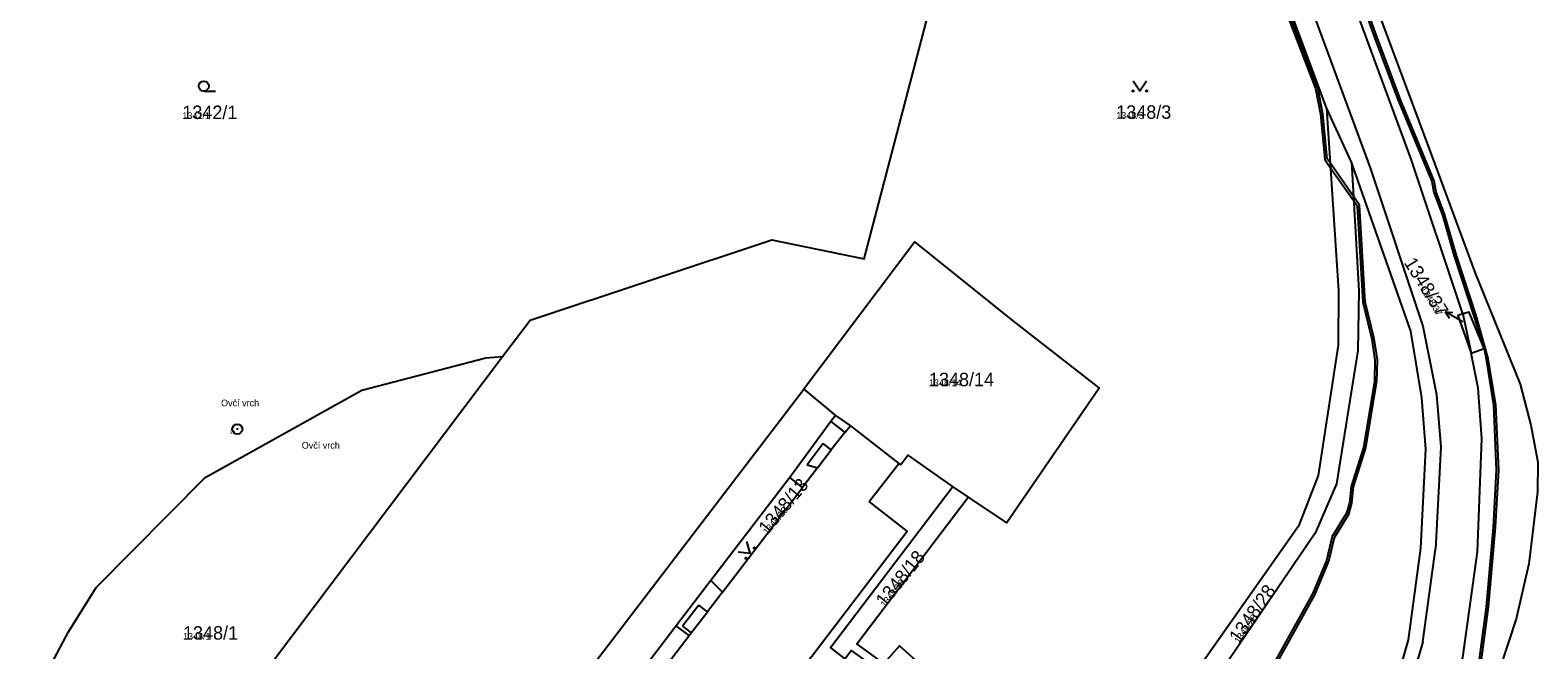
# Model space of a CAD drawing. Extents: x -763628 to -761565, y -976033 to -973833.
# Drawn here: x -762526.1 to -762302.1, y -975580.9 to -975488.8 of the extents above; entities that cross this region are included whole.
import ezdxf

# ---------------------------------------------------------------- set-up
doc = ezdxf.new("R2010")
doc.units = 0
for name, color, linetype in [('KN_cisla parcel 1000', 7, 'Continuous'), ('KN_cisla parcel 500', 7, 'Continuous'), ('KN_cisla parcel znacky', 7, 'Continuous'), ('KN_hranice parcel', 7, 'Continuous'), ('KN_popisy', 7, 'Continuous'), ('KN_vecna bremena', 7, 'Continuous'), ('KN_vnitrni kresba parcel', 7, 'Continuous'), ('KN_znacky bodu BP', 7, 'Continuous'), ('KN_znacky kultur', 7, 'Continuous')]:
    doc.layers.add(name, color=color, linetype=linetype)

msp = doc.modelspace()

# ---------------------------------------------------------------- linework, layer by layer
at = {"layer": 'KN_cisla parcel znacky'}
for p, q in [((-762313.27, -975532.17), (-762315.87, -975530.67)), ((-762315.87, -975530.67), (-762314.75, -975530.74)), ((-762315.87, -975530.67), (-762315.25, -975531.6))]:
    msp.add_line(p, q, dxfattribs=at)
at = {"layer": 'KN_hranice parcel'}
for p, q in [((-762329.78, -975508.4), (-762333.52, -975500.37)), ((-762313.26, -975530.98), (-762320.9, -975507.99)), ((-762310.99, -975542.02), (-762312, -975536.8)), ((-762411.19, -975542.16), (-762406.47, -975546.08)), ((-762413.28, -975555.29), (-762425, -975570.59)), ((-762389.05, -975556.64), (-762386.74, -975558.2)), ((-762425, -975570.59), (-762430.13, -975577.3)), ((-762430.13, -975577.3), (-762448.29, -975601.15))]:
    msp.add_line(p, q, dxfattribs=at)
for points in [[(-762320.9, -975507.99), (-762333.29, -975474.33), (-762340.09, -975455.85)], [(-762455.93, -975537.3), (-762451.86, -975531.9), (-762415.93, -975519.94), (-762402.23, -975522.78), (-762385.32, -975458.25)], [(-762333.52, -975500.37), (-762342, -975477.5), (-762348.7, -975458.93)], [(-762330.42, -975473.69), (-762317.88, -975507.36), (-762311.41, -975524.93), (-762304.73, -975541.39), (-762303.13, -975547.49), (-762302.1, -975552.98), (-762302.14, -975557.43), (-762303.44, -975568.09), (-762305.3, -975576.28), (-762307.74, -975583.66), (-762309.01, -975587.42), (-762310.14, -975590.81), (-762313.38, -975597.97), (-762313.79, -975598.72), (-762314.8, -975600.39)], [(-762333.52, -975500.37), (-762331.73, -975527.56), (-762331.77, -975535.62), (-762334.73, -975554.96), (-762337.68, -975562.5), (-762353.31, -975584.75), (-762360.52, -975596)], [(-762403.81, -975712.92), (-762399.17, -975708.68), (-762393.45, -975701.6), (-762387.86, -975693.06), (-762358.94, -975647.65), (-762334.55, -975608.66), (-762324.91, -975591.91), (-762321.34, -975579.42), (-762319.47, -975565.76), (-762318.73, -975551.05), (-762319.32, -975543.45), (-762320.98, -975533.54), (-762329.78, -975508.4)], [(-762329.78, -975508.4), (-762328.72, -975527.52), (-762328.86, -975536.39), (-762332.01, -975556.21), (-762335.17, -975563.53), (-762350.94, -975586.68), (-762357.89, -975597.63)], [(-762386.74, -975558.2), (-762381.07, -975562.01), (-762367.28, -975541.95), (-762380.07, -975531.99), (-762394.69, -975520.26), (-762411.19, -975542.16)], [(-762313.26, -975530.98), (-762314, -975531.2), (-762312, -975536.8)], [(-762312, -975536.8), (-762310.1, -975536.1), (-762312.3, -975530.7), (-762313.26, -975530.98)], [(-762553.82, -975649.08), (-762540.26, -975615.89), (-762533.07, -975601.88), (-762520.45, -975578.19), (-762516.33, -975571.64), (-762500.14, -975555.29), (-762476.88, -975542.28), (-762458.41, -975537.49), (-762455.93, -975537.3)], [(-762527.07, -975640.34), (-762529.3, -975634.7), (-762455.93, -975537.3)], [(-762512.11, -975678.16), (-762511.09, -975674.43), (-762503.29, -975662.52), (-762500.18, -975658.38), (-762473.49, -975623.68), (-762452.78, -975596.61), (-762429.65, -975566.34), (-762411.19, -975542.16)], [(-762391.57, -975714.65), (-762389.96, -975710.93), (-762383.53, -975701.73), (-762380.79, -975697.54), (-762351.91, -975652.23), (-762327.24, -975612.72), (-762317.38, -975595.61), (-762313.24, -975582.02), (-762311.08, -975566.3), (-762310.44, -975549.48), (-762310.99, -975542.02)], [(-762406.47, -975546.08), (-762407.16, -975546.96), (-762413.28, -975555.29)], [(-762406.47, -975546.08), (-762404.26, -975547.62), (-762397.08, -975553.2)], [(-762397.08, -975553.2), (-762396.75, -975553.34), (-762395.7, -975551.96), (-762389.05, -975556.64)], [(-762412.23, -975584.75), (-762395.81, -975563.25), (-762401.47, -975558.86), (-762397.08, -975553.2)], [(-762425, -975570.59), (-762423.26, -975572.31), (-762411.37, -975556.77), (-762413.28, -975555.29)], [(-762389.05, -975556.64), (-762407.21, -975580.61), (-762405.09, -975582.21), (-762404.14, -975580.97), (-762400.11, -975583.85), (-762402.31, -975586.63), (-762399.83, -975588.71), (-762394.6, -975582.41), (-762396.95, -975580.28), (-762399.28, -975582.91), (-762403.29, -975579.99), (-762386.74, -975558.2)], [(-762448.29, -975601.15), (-762446.44, -975602.58), (-762428.22, -975578.78), (-762430.13, -975577.3)]]:
    msp.add_lwpolyline(points, dxfattribs=at)
at = {"layer": 'KN_vecna bremena'}
for points in [[(-762347.41, -975465.51), (-762335.12, -975497.45), (-762334.38, -975501.28), (-762333.76, -975508.03), (-762332.94, -975509.2), (-762329.46, -975514.16), (-762328.93, -975514.92), (-762328.1, -975529.23), (-762326.75, -975534.73), (-762326.31, -975537.82), (-762326.37, -975540.94), (-762328.02, -975550.81), (-762329.82, -975556.6), (-762330.1, -975559.04), (-762330.51, -975560.58), (-762332.65, -975564.03), (-762333.52, -975567.61), (-762335.57, -975572.56), (-762346.03, -975591.41)], [(-762327.68, -975550.89), (-762326.03, -975540.98), (-762325.95, -975537.8), (-762326.41, -975534.67), (-762327.76, -975529.17), (-762328.59, -975514.8), (-762329.5, -975513.51), (-762332.98, -975508.53), (-762333.42, -975507.91), (-762334.04, -975501.24), (-762334.78, -975497.35), (-762347.09, -975465.39)], [(-762332.39, -975472.88), (-762326.52, -975489.48), (-762322.89, -975499.12), (-762317.83, -975511.27), (-762317.56, -975512.95), (-762316.29, -975516.29), (-762314.54, -975522.38), (-762311.6, -975531.31), (-762310.1, -975536.1), (-762309.8, -975537.68), (-762308.69, -975544.53), (-762308.27, -975554.2), (-762308.74, -975562.66), (-762309.79, -975574.51), (-762311.17, -975584.87)], [(-762310.83, -975584.95), (-762309.45, -975574.55), (-762308.4, -975562.68), (-762307.91, -975554.2), (-762308.35, -975544.49), (-762309.46, -975537.6), (-762311.26, -975531.21), (-762314.2, -975522.28), (-762315.95, -975516.17), (-762317.22, -975512.85), (-762317.49, -975511.17), (-762322.57, -975499), (-762326.2, -975489.36), (-762332.07, -975472.76)], [(-762345.73, -975591.61), (-762335.25, -975572.72), (-762333.18, -975567.71), (-762332.33, -975564.17), (-762330.19, -975560.72), (-762329.76, -975559.1), (-762329.48, -975556.68), (-762327.68, -975550.89)]]:
    msp.add_lwpolyline(points, dxfattribs=at)
at = {"layer": 'KN_vnitrni kresba parcel'}
for p, q in [((-762338.89, -975476.99), (-762327.02, -975509.28)), ((-762327.02, -975509.28), (-762319.19, -975532.79)), ((-762313.26, -975530.98), (-762313.19, -975531.19)), ((-762313.19, -975531.19), (-762312, -975536.8)), ((-762319.19, -975532.79), (-762317.17, -975542.92)), ((-762317.17, -975542.92), (-762316.5, -975550.76)), ((-762407.16, -975546.96), (-762405.09, -975548.57)), ((-762405.09, -975548.57), (-762404.26, -975547.62)), ((-762405.09, -975548.57), (-762407.1, -975551.19)), ((-762408.3, -975550.25), (-762410.69, -975553.39)), ((-762409.13, -975553.85), (-762407.1, -975551.19)), ((-762407.1, -975551.19), (-762408.3, -975550.25)), ((-762316.5, -975550.76), (-762317.3, -975565.95)), ((-762409.13, -975553.85), (-762411.37, -975556.77)), ((-762410.69, -975553.39), (-762409.13, -975553.85)), ((-762319.18, -975579.72), (-762317.3, -975565.95)), ((-762423.26, -975572.31), (-762425.51, -975575.24)), ((-762426.79, -975574.24), (-762429.21, -975577.37)), ((-762425.51, -975575.24), (-762426.79, -975574.24)), ((-762427.91, -975578.38), (-762425.51, -975575.24)), ((-762429.21, -975577.37), (-762427.91, -975578.38)), ((-762428.22, -975578.78), (-762427.91, -975578.38)), ((-762319.18, -975579.72), (-762323.13, -975593.24))]:
    msp.add_line(p, q, dxfattribs=at)
at = {"layer": 'KN_znacky bodu BP'}
for radius in [0.75, 0.03]:
    msp.add_circle((-762495.36, -975548.08), radius, dxfattribs=at)
at = {"layer": 'KN_znacky kultur'}
msp.add_line((-762500.35, -975497.86), (-762498.6, -975497.86), dxfattribs=at)
for points in [[(-762362.24, -975496.33), (-762361.24, -975497.83), (-762360.24, -975496.33)], [(-762420.94, -975566.31), (-762419.15, -975566.51), (-762419.66, -975564.78)]]:
    msp.add_lwpolyline(points, dxfattribs=at)
for centre, radius in [((-762500.35, -975497.11), 0.75), ((-762362.24, -975497.83), 0.1), ((-762360.24, -975497.83), 0.1), ((-762418.51, -975565.74), 0.1), ((-762419.79, -975567.28), 0.1)]:
    msp.add_circle(centre, radius, dxfattribs=at)

# ---------------------------------------------------------------- texts
at = {"layer": 'KN_cisla parcel 1000'}
for s, p in [('1342/1', (-762503.53, -975502.01)), ('1348/3', (-762364.75, -975501.98)), ('1348/14', (-762392.58, -975541.71)), ('1348/1', (-762503.43, -975579.37))]:
    msp.add_text(s, height=2, dxfattribs=at).set_placement(p)
for s, rotation, p in [('1348/37', 302, (-762322.07, -975523.35)), ('1348/13', 50, (-762416.57, -975563.86)), ('1348/18', 51, (-762399.11, -975574.66)), ('1348/28', 55, (-762346.49, -975580.02))]:
    msp.add_text(s, height=2, rotation=rotation, dxfattribs=at).set_placement(p)
at = {"layer": 'KN_cisla parcel 500'}
for s, p in [('1342/1', (-762503.53, -975502.01)), ('1348/3', (-762364.75, -975501.98)), ('1348/14', (-762392.58, -975541.71)), ('1348/1', (-762503.43, -975579.37))]:
    msp.add_text(s, height=1, dxfattribs=at).set_placement(p)
for s, rotation, p in [('1348/37', 302, (-762319.61, -975527.28)), ('1348/13', 50, (-762416.57, -975563.86)), ('1348/18', 51, (-762399.11, -975574.66)), ('1348/28', 55, (-762346.49, -975580.02))]:
    msp.add_text(s, height=1, rotation=rotation, dxfattribs=at).set_placement(p)
at = {"layer": 'KN_popisy'}
for p in [(-762497.77, -975544.7), (-762485.78, -975551)]:
    msp.add_text('Ovčí vrch', height=1, dxfattribs=at).set_placement(p)
at = {"layer": 'KN_znacky bodu BP'}
msp.add_text('20', height=0.5, dxfattribs=at).set_placement((-762496.44, -975548.83))

doc.saveas('drawing.dxf')
